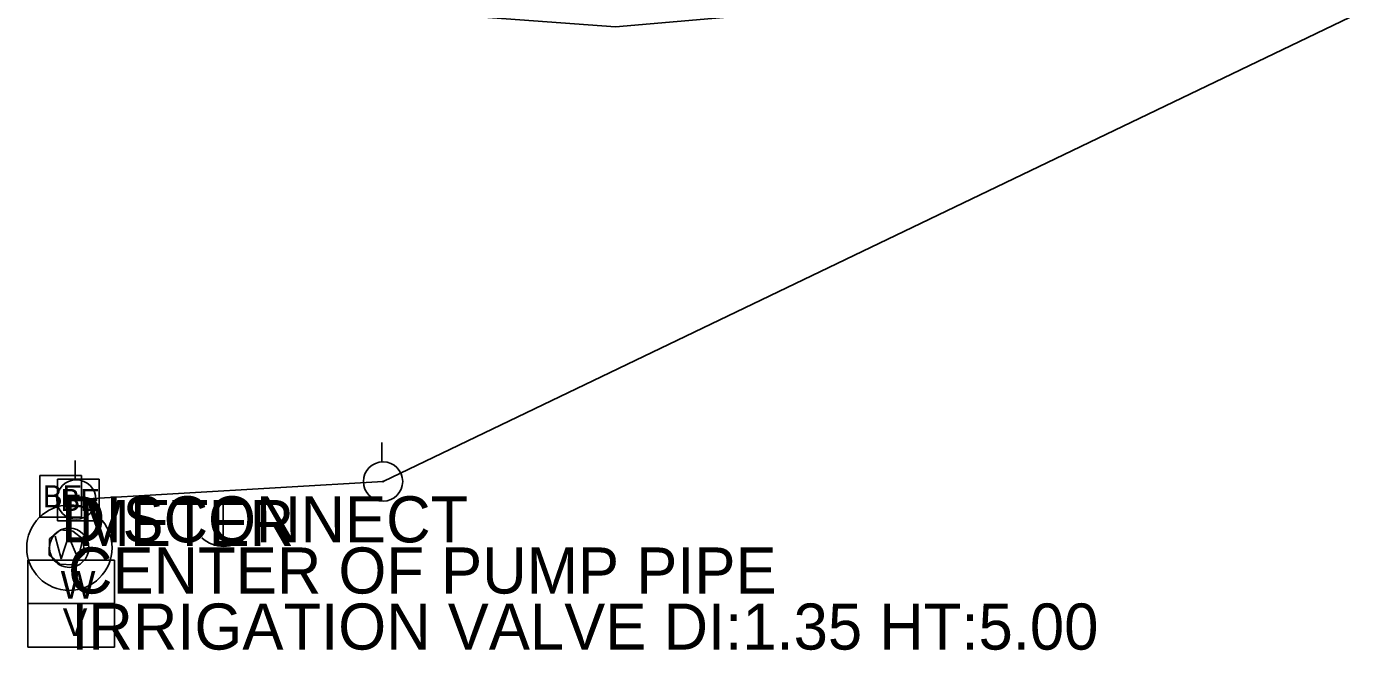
# Model space of a CAD drawing. Extents: x 1676038 to 1677961, y 226475 to 233854.
# Drawn here: x 1676992.6 to 1677137.5, y 229071.7 to 229139.3 of the extents above; entities that cross this region are included whole.
import ezdxf

# ---------------------------------------------------------------- set-up
doc = ezdxf.new("R2010")
doc.units = 0
for name, color, linetype in [('S_EDGE_CONCRETE', 7, 'Continuous'), ('S_ELECTRIC_UTILITIES', 7, 'Continuous'), ('S_ELECTRIC_UTILITIES_ANNOT', 7, 'Continuous'), ('S_STREAM', 7, 'Continuous'), ('S_UTILITY_POLE', 7, 'Continuous'), ('S_UTL_PT_SYM', 7, 'Continuous'), ('S_WATER_UTILITIES', 7, 'Continuous'), ('S_WATER_UTILITIES_ANNOT', 7, 'Continuous'), ('S_WATER_WELL_ANNOT', 7, 'Continuous')]:
    doc.layers.add(name, color=color, linetype=linetype)

msp = doc.modelspace()

# ---------------------------------------------------------------- linework, layer by layer
at = {"layer": 'S_EDGE_CONCRETE'}
msp.add_lwpolyline([(1676995.02, 229083.8), (1676994.98, 229082.04), (1676996.14, 229081.03), (1676997.58, 229080.98), (1676998.8, 229082.15), (1676998.7, 229083.76), (1676997.57, 229084.6), (1676996.22, 229084.77)], close=True, dxfattribs=at)
at = {"layer": 'S_ELECTRIC_UTILITIES'}
for p, q in [((1677278.13, 229208.63), (1677031.23, 229090)), ((1677031.23, 229090), (1676997.94, 229088.05))]:
    msp.add_line(p, q, dxfattribs=at)
for points in [[(1676994, 229086.15), (1676994, 229090.65), (1676998.5, 229090.65), (1676998.5, 229086.15)], [(1676995.91, 229085.75), (1676995.91, 229090.25), (1677000.41, 229090.25), (1677000.41, 229085.75)]]:
    msp.add_lwpolyline(points, close=True, dxfattribs=at)
at = {"layer": 'S_STREAM'}
msp.add_lwpolyline([(1677077.37, 229141.12), (1677056.44, 229139.33), (1677041.62, 229140.43)], dxfattribs=at)
at = {"layer": 'S_UTILITY_POLE'}
for p, q in [((1677031.11, 229092.14), (1677031.11, 229094.25)), ((1676997.81, 229090.19), (1676997.81, 229092.3)), ((1677013.87, 229087.68), (1677013.87, 229082.95))]:
    msp.add_line(p, q, dxfattribs=at)
for centre in [(1677031.23, 229090), (1676997.94, 229088.05)]:
    msp.add_circle(centre, 2.13, dxfattribs=at)
msp.add_arc((1677013.93, 229086.37), 3.41, 226.3972, 313.6028, dxfattribs=at)
at = {"layer": 'S_UTL_PT_SYM'}
for points in [[(1677031.23, 229090), (1677031.23, 229090.05), (1677031.23, 229090), (1677031.18, 229090), (1677031.23, 229090), (1677031.23, 229089.95), (1677031.23, 229090), (1677031.28, 229090)], [(1676997.94, 229088.05), (1676997.94, 229088.1), (1676997.94, 229088.05), (1676997.89, 229088.05), (1676997.94, 229088.05), (1676997.94, 229088), (1676997.94, 229088.05), (1676997.99, 229088.05)]]:
    msp.add_lwpolyline(points, dxfattribs=at)
at = {"layer": 'S_WATER_UTILITIES'}
for p, q in [((1676995.63, 229084.08), (1676996.29, 229081.6)), ((1676996.29, 229081.6), (1676997.1, 229084.08)), ((1676997.1, 229084.08), (1676998.15, 229081.6)), ((1676998.15, 229081.6), (1676998.73, 229084.12)), ((1676992.68, 229081.46), (1677002.1, 229081.46)), ((1676992.68, 229072.04), (1676992.68, 229081.46)), ((1677002.1, 229081.46), (1677002.1, 229072.04)), ((1676992.68, 229076.77), (1677002.1, 229076.77)), ((1677002.1, 229072.04), (1676992.68, 229072.04))]:
    msp.add_line(p, q, dxfattribs=at)
for centre, radius in [((1676997.19, 229082.82), 4.63), ((1676997.16, 229082.82), 2.13)]:
    msp.add_circle(centre, radius, dxfattribs=at)

# ---------------------------------------------------------------- texts
at = {"layer": 'S_ELECTRIC_UTILITIES'}
for p in [(1676994.31, 229087.2), (1676996.22, 229086.8)]:
    msp.add_text('BE', height=2.4, rotation=360, dxfattribs=at).set_placement(p)
at = {"layer": 'S_ELECTRIC_UTILITIES_ANNOT'}
for s, p in [('DISCONNECT', (1676996.27, 229083.4)), ('METER', (1676998.18, 229083))]:
    msp.add_text(s, height=5, dxfattribs=at).set_placement(p)
at = {"layer": 'S_WATER_UTILITIES'}
for s, p in [('W', (1676996.24, 229077.3)), ('V', (1676996.47, 229073.24))]:
    msp.add_text(s, height=3, rotation=360, dxfattribs=at).set_placement(p)
at = {"layer": 'S_WATER_UTILITIES_ANNOT'}
msp.add_text('IRRIGATION VALVE DI:1.35 HT:5.00', height=5, dxfattribs=at).set_placement((1676997.39, 229071.77))
at = {"layer": 'S_WATER_WELL_ANNOT'}
msp.add_text('CENTER OF PUMP PIPE', height=5, dxfattribs=at).set_placement((1676997.04, 229077.85))

doc.saveas('drawing.dxf')
